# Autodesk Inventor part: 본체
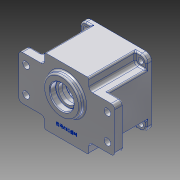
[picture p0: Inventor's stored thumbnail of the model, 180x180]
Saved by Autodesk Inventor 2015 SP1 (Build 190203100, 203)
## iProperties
Created: 2014-12
Part Number: 본체
Material: 알루미늄 6061
Document SubType Name: Modeling
Designer: kjc
Density: 2.7 g/cm^3
Appearance: 알루미늄 - 평지
Mass: 702.727 g
Surface Area: 673.143 cm^2
Volume: 260.269 cm^3
Author: kjc
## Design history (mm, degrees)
sketch "스케치1"
  geometry: L1 (-30, 45)-(30, 45); L2 (30, 45)-(30, -45); L3 (30, -45)-(-30, -45); L4 (-30, -45)-(-30, 45); L5 (-65, 30)-(65, 30); L6 (65, 30)-(65, -30); L7 (65, -30)-(-65, -30); L8 (-65, -30)-(-65, 30); 5 further points
  constraints: 16 end point, 4 midpoint, 4 parallel, 2 horizontal, 2 horizontal alignment, 2 perpendicular, 2 vertical alignment
  dimensions: "d0" = 60 distance of L1.start L1.end; "d1" = 90 distance of L1.end L2.end; "d2" = 130 distance between parallel lines of L6 L8; "d3" = 60 distance of L7.end L5.start
extrude "돌출1" new body sketch "스케치1" distance "d4" = 12; taper "d5" = 0 deg
fillet "모깎기1" dims "d6" = 5
fillet "모깎기2" dims "d7" = 2
sketch "스케치2"
  geometry: L1 (30, -43)-(30, -35) reference; L2 (35, -30)-(60, -30) reference; L3 (65, -25)-(65, 25) reference; L4 (60, 30)-(35, 30) reference; L5 (30, 35)-(30, 43) reference; L6 (28, 45)-(-28, 45) reference; L7 (-30, 43)-(-30, 35) reference; L8 (-35, 30)-(-60, 30) reference; L9 (-65, 25)-(-65, -25) reference; L10 (-60, -30)-(-35, -30) reference; L11 (-30, -35)-(-30, -43) reference; L12 (-28, -45)-(28, -45) reference; L13 (-60, 30)-(-35, 30) reference; L14 (-45, 30)-(-45, -30); L15 (35, 30)-(60, 30) reference; L16 (45, 30)-(45, -30); L17 (60, -30)-(35, -30) reference; A1 r 2 centre (28, -43) between (28, -45) and (30, -43) reference; A2 r 5 centre (35, -35) between (35, -30) and (30, -35) reference; A3 r 5 centre (60, -25) between (60, -30) and (65, -25) reference; A4 r 5 centre (60, 25) between (65, 25) and (60, 30) reference; A5 r 5 centre (35, 35) between (30, 35) and (35, 30) reference; A6 r 2 centre (28, 43) between (30, 43) and (28, 45) reference; A7 r 2 centre (-28, 43) between (-28, 45) and (-30, 43) reference; A8 r 5 centre (-35, 35) between (-35, 30) and (-30, 35) reference; A9 r 5 centre (-60, 25) between (-60, 30) and (-65, 25) reference; A10 r 5 centre (-60, -25) between (-65, -25) and (-60, -30) reference; A11 r 5 centre (-35, -35) between (-30, -35) and (-35, -30) reference; A12 r 2 centre (-28, -43) between (-30, -43) and (-28, -45) reference; 3 further points
  constraints: 4 end point, 4 point on line, 2 perpendicular, 1 horizontal alignment, 1 vertical alignment
  dimensions: "d10" = 45 distance from line of L14 point (0, 0); "d11" = 45 distance from line of point (0, 0) L16 (= d10)
extrude "돌출2" join sketch "스케치2" distance "d12" = 51; taper "d13" = 0 deg
sketch "스케치3"
  geometry: L1 (-45, 45)-(45, 45); L2 (45, 45)-(45, -45); L3 (45, -45)-(-45, -45); L4 (-45, -45)-(-45, 45); 3 further points
  constraints: 8 end point, 2 midpoint, 2 parallel, 1 horizontal, 1 horizontal alignment, 1 perpendicular, 1 vertical alignment
  dimensions: "d14" = 90 distance of L1.start L1.end; "d15" = 90 distance of L1.end L2.end (= d14)
extrude "돌출3" join sketch "스케치3" distance "d16" = 7; taper "d17" = 0 deg
fillet "모깎기3" dims "d18" = 8
fillet "모깎기4" dims "d19" = 2
sketch "스케치4"
  geometry: C1 r 25 at (0, 11); 1 further point
  constraints: 1 centre point, 1 vertical alignment
  dimensions: "d20" = 50 diameter of C1; "d21" = 11 distance of point (0, 0) C1.centre
extrude "돌출4" join sketch "스케치4" distance "d22" = 7; taper "d23" = 0 deg
fillet "모깎기5" dims "d24" = 2
sketch "스케치5"
  geometry: C1 r 23 at (0, 0) reference; C2 r 16 at (0, 0); 1 further point
  constraints: 1 centre point, 1 coincident
  dimensions: "d25" = 32 diameter of C2
extrude "돌출5" cut sketch "스케치5" distance "d26" = 8; taper "d27" = 0 deg
sketch "스케치6"
  geometry: C1 r 16 at (0, 0) reference; C2 r 12.5 at (0, 0); 1 further point
  constraints: 1 centre point, 1 coincident
  dimensions: "d28" = 25 diameter of C2
extrude "돌출6" cut sketch "스케치6" distance "d29" = 5; taper "d30" = 0 deg
sketch "스케치8"
  geometry: C1 r 40 at (0, 0); 1 further point
  constraints: 1 centre point, 1 coincident
  dimensions: "d34" = 80 diameter of C1
extrude "돌출8" cut sketch "스케치8" distance "d35" = 9; taper "d36" = 0 deg
sketch "스케치9"
  geometry: C1 r 40 at (0, 0) reference; C2 r 39 at (0, 0)
  constraints: 1 centre point, 1 coincident
  dimensions: "d37" = 78 diameter of C2
extrude "돌출9" cut sketch "스케치9" distance "d38" = 52; taper "d39" = 0 deg
sketch "스케치10"
  geometry: C1 r 39 at (0, 0) reference; C2 r 20.5 at (0, 11); C3 r 14 at (0, -20)
  constraints: 2 centre point
  dimensions: "d40" = 41 diameter of C2; "d41" = 28 diameter of C3; "d42" = 11 distance of C1.centre C2.centre; "d43" = 20 distance of C3.centre C1.centre
extrude "돌출10" join sketch "스케치10" distance "d44" = 7; taper "d45" = 0 deg
fillet "모깎기6" dims "d46" = 3
sketch "스케치11"
  geometry: C1 r 17.5 at (0, 11); A1 r 20.5 centre (0, 11) between (11.115, -6.225) and (-11.115, -6.225) reference; 1 further point
  constraints: 1 centre point, 1 coincident
  dimensions: "d47" = 35 diameter of C1
extrude "돌출11" cut sketch "스케치11" distance "d48" = 10; taper "d49" = 0 deg
sketch "스케치12"
  geometry: C1 r 11 at (0, -20); A1 r 14 centre (0, -20) between (-10.493, -10.732) and (10.493, -10.732) reference; 1 further point
  constraints: 1 centre point, 1 coincident
  dimensions: "d50" = 22 diameter of C1
extrude "돌출12" cut sketch "스케치12" distance "d51" = 7; taper "d52" = 0 deg
sketch "스케치13"
  geometry: L1 (0, 0)-(24.749, 24.749); L2 (60, 30)-(47, 30) reference; L3 (24.749, 24.749)-(21.92, 27.577); L4 (21.92, 27.577)-(24.603, 30.26); L5 (27.577, 21.92)-(30.26, 24.603); C1 r 40 at (0, 0) reference; A1 r 4 centre (24.749, 24.749) between (21.92, 27.577) and (27.577, 21.92); A2 r 39 centre (0, 0) between (24.603, 30.26) and (30.26, 24.603) reference
  constraints: 8 end point, 4 point on circle, 1 centre point, 1 symmetric about line
  dimensions: "d53" = 8 diameter of A1; "d54" = 45 deg angle of L2 L1; "d55" = 35 distance of L1.start L1.end; "d56" = 90 deg angle of L1 L3; "d57" = 90 deg angle of L3 L4; "d58" = 90 deg angle of L5 L3
extrude "돌출13" join sketch "스케치13" stored distance "d59" = 7; taper "d60" = 0 deg
fillet "모깎기7" dims "d61" = 3.5
fillet "모깎기8" dims "d65" = 2
sketch "스케치14"
  geometry: C1 r 11 at (0, 0) reference; C2 r 9.5 at (0, 0); 1 further point
  constraints: 1 centre point, 1 coincident
  dimensions: "d66" = 19 diameter of C2
extrude "돌출14" cut sketch "스케치14" distance "d67" = 1; taper "d68" = 0 deg
fillet "모깎기9" dims "d69" = 1
fillet "모깎기10" dims "d70" = 0.3
chamfer "모따기1" distance "d71" = 1; stored, may be unused: second distance "d72" = 2, angle "d73" = 45 deg
sketch "스케치15"
  geometry: A1 r 8 centre (37, -37) between (37, -45) and (45, -37) reference; A2 r 8 centre (37, 37) between (45, 37) and (37, 45) reference; A3 r 8 centre (-37, 37) between (-37, 45) and (-45, 37) reference; A4 r 8 centre (-37, -37) between (-45, -37) and (-37, -45) reference; 4 further points
  constraints: 4 coincident
hole "구멍1" sketch "스케치15" at (-37, 37), (37, 37), (37, -37), (-37, -37) diameter "d74" = 7; stored, may be unused: countersink angle "d78" = 90 deg, drill point angle "d80" = 118 deg; dims "d75" = 6, "d76" = 4, "d77" = 2, "d79" = 8
sketch "스케치16"
  geometry: 5 further points
  constraints: 2 horizontal alignment, 2 vertical alignment
  dimensions: "d81" = 110 distance of point (55, 17.5) point (-55, 17.5); "d82" = 35 distance of point (55, -17.5) point (55, 17.5); "d83" = 17.5 vertical distance of point (0, 0) point (55, 17.5) (= 0.5 x d82); "d84" = 55 horizontal distance of point (0, 0) point (-55, 17.5) (= 0.5 x d81)
hole "구멍2" sketch "스케치16" at (-55, 17.5), (55, 17.5), (55, -17.5), (-55, -17.5) diameter "d85" = 9; stored, may be unused: countersink angle "d89" = 90 deg, drill point angle "d91" = 118 deg; dims "d86" = 6, "d87" = 4, "d88" = 2, "d90" = 8
sketch "스케치17"
  geometry: A1 r 4 centre (24.749, 24.749) between (21.809, 27.462) and (27.462, 21.809) reference; A2 r 4 centre (24.749, -24.749) between (27.462, -21.809) and (21.809, -27.462) reference; A3 r 4 centre (-24.749, -24.749) between (-21.809, -27.462) and (-27.462, -21.809) reference; A4 r 4 centre (-24.749, 24.749) between (-27.462, 21.809) and (-21.809, 27.462) reference; 4 further points
  constraints: 4 coincident
hole "구멍3" sketch "스케치17" at (-24.749, 24.749), (24.749, 24.749), (24.749, -24.749), (-24.749, -24.749) diameter "d92" = 3.242; stored, may be unused: countersink angle "d96" = 90 deg, drill point angle "d98" = 118 deg; dims "d93" = 12, "d94" = 4, "d95" = 2, "d97" = 15
sketch "스케치18"
  geometry: L1 (-28, -45)-(28, -45) reference; L2 (-14.518, -27.899)-(14.518, -27.899); L3 (14.518, -27.899)-(14.518, -32.101); L4 (14.518, -32.101)-(-14.518, -32.101); L5 (-14.518, -32.101)-(-14.518, -27.899); L6 (-14.518, -32.101)-(14.518, -27.899); C1 r 27 at (0, 11) reference; 2 further points
  constraints: 2 end point, 1 horizontal, 1 midpoint, 1 vertical alignment, 2 other
  dimensions: "d99" = 15 distance from line of L1 point (0, -30)
feature "엠보싱1" sketch "스케치18" dims "d0" = 60, "d1" = 90, "d2" = 130, "d3" = 60, "d100" = 0.5, "d101" = 0
node "솔리드1"
pattern_circular "원형 패턴1" dims angle "d63" = 360 deg
node "투영된 루프1"
node "투영된 루프2"
node "투영된 루프3"
